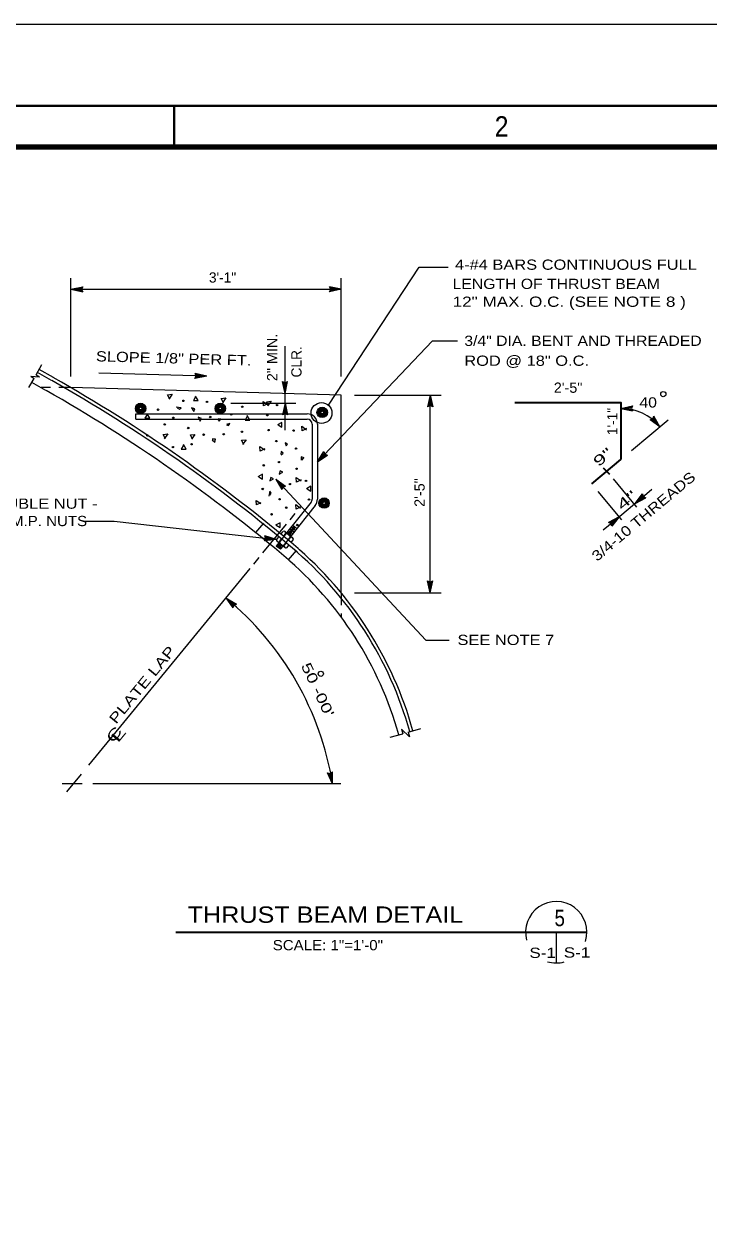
# Model space of a CAD drawing. Extents: x -24.3 to 17.7, y -17.6 to 12.4.
# Drawn here: x -1.17 to 7.19, y -2.28 to 12.39 of the extents above; entities that cross this region are included whole.
import ezdxf
from ezdxf.enums import TextEntityAlignment as Align

# ---------------------------------------------------------------- set-up
doc = ezdxf.new("R2010")
doc.units = 0
doc.header["$LTSCALE"] = 0.05
doc.linetypes.add('MEDIUM_DASHED', pattern=[4.5, 3, -1.5])
doc.layers.add('1', color=7, linetype='Continuous', lineweight=13)
doc.layers.add('2', color=7, linetype='Continuous', lineweight=13)

msp = doc.modelspace()

# ---------------------------------------------------------------- linework, layer by layer
at = {"layer": '1', "lineweight": 40}
msp.add_line((0.65731, 11.3894), (0.65731, 10.8894), dxfattribs=at)
at = {"layer": '1'}
for p, q in [((2.54531, 7.7364), (3.65231, 9.4234)), ((3.65231, 9.4234), (4.00431, 9.4234)), ((-0.60169, 8.0884), (-0.60169, 9.2884)), ((2.70031, 8.0884), (2.70031, 9.2884)), ((-0.60169, 9.1534), (-0.45769, 9.1844)), ((-0.60169, 9.1534), (2.70031, 9.1534)), ((-0.60169, 9.1534), (-0.45769, 9.1224)), ((-0.56469, 9.1534), (-0.47069, 9.1734)), ((-0.56469, 9.1534), (-0.47069, 9.1334)), ((-0.52869, 9.1534), (-0.48369, 9.1634)), ((-0.52869, 9.1534), (-0.48369, 9.1444)), ((-0.48369, 9.1634), (-0.48769, 9.1534)), ((-0.48769, 9.1534), (-0.48369, 9.1444)), ((-0.47069, 9.1734), (-0.47969, 9.1534)), ((-0.47969, 9.1534), (-0.47069, 9.1334)), ((2.70031, 9.1534), (2.55631, 9.1844)), ((2.70031, 9.1534), (2.55631, 9.1224)), ((2.66331, 9.1534), (2.56931, 9.1734)), ((2.57831, 9.1534), (2.56931, 9.1734)), ((2.66331, 9.1534), (2.56931, 9.1334)), ((2.56931, 9.1334), (2.57831, 9.1534)), ((2.62731, 9.1534), (2.58231, 9.1624)), ((2.58631, 9.1534), (2.58231, 9.1624)), ((2.62731, 9.1534), (2.58231, 9.1434)), ((2.58231, 9.1434), (2.58631, 9.1534)), ((2.40831, 7.0454), (3.81431, 8.5234)), ((3.81431, 8.5234), (4.11731, 8.5234)), ((-1.02669, 8.1104), (-0.95569, 8.2334)), ((-1.09369, 8.0914), (-1.05169, 8.0654)), ((-1.09369, 8.0914), (-0.98469, 8.0844)), ((-1.02669, 8.1104), (-0.98469, 8.0844)), ((-1.11669, 7.9524), (-1.05169, 8.0654)), ((2.01331, 7.8824), (1.98231, 8.0264)), ((2.01331, 7.9194), (1.99331, 8.0134)), ((1.99331, 8.0134), (2.01331, 8.0044)), ((2.01331, 7.9554), (2.00331, 8.0004)), ((2.00331, 8.0004), (2.01331, 7.9964)), ((2.01331, 7.8824), (2.04431, 8.0264)), ((2.01331, 7.9194), (2.03331, 8.0134)), ((2.01331, 8.0044), (2.03331, 8.0134)), ((2.01331, 7.9554), (2.02231, 8.0004)), ((2.01331, 7.9964), (2.02231, 8.0004)), ((2.86131, 7.8624), (3.91831, 7.8624)), ((3.78531, 7.8624), (3.75431, 7.7184)), ((3.78531, 7.8254), (3.76531, 7.7314)), ((3.78531, 7.7894), (3.77631, 7.7444)), ((3.78531, 5.4494), (3.78531, 7.8624)), ((3.78531, 7.8624), (3.81631, 7.7184)), ((3.78531, 7.8254), (3.80531, 7.7314)), ((3.78531, 7.7894), (3.79531, 7.7444)), ((1.34931, 7.7624), (2.14531, 7.7624)), ((2.01331, 7.7624), (1.98231, 7.6184)), ((2.01331, 7.7254), (1.99331, 7.6314)), ((2.01331, 7.6404), (1.99331, 7.6314)), ((2.01331, 7.6894), (2.00431, 7.6444)), ((2.01331, 7.6484), (2.00431, 7.6444)), ((2.01331, 7.7624), (2.04431, 7.6184)), ((2.01331, 7.4344), (2.01331, 7.7624)), ((2.01331, 7.7254), (2.03331, 7.6314)), ((2.01331, 7.6894), (2.02331, 7.6444)), ((2.02331, 7.6444), (2.01331, 7.6484)), ((2.03331, 7.6314), (2.01331, 7.6404)), ((3.78531, 7.7404), (3.76531, 7.7314)), ((3.78531, 7.7484), (3.77631, 7.7444)), ((3.79531, 7.7444), (3.78531, 7.7484)), ((3.80531, 7.7314), (3.78531, 7.7404)), ((6.11231, 7.6994), (6.25631, 7.7304)), ((6.11231, 7.6994), (6.25631, 7.6684)), ((6.14931, 7.6994), (6.24331, 7.7194)), ((6.14931, 7.6994), (6.24331, 7.6794)), ((6.18531, 7.6994), (6.23031, 7.7094)), ((6.18531, 7.6994), (6.23031, 7.6904)), ((6.23031, 7.7094), (6.22631, 7.6994)), ((6.22631, 7.6994), (6.23031, 7.6904)), ((6.24331, 7.7194), (6.23431, 7.6994)), ((6.23431, 7.6994), (6.24331, 7.6794)), ((6.24231, 7.1834), (6.69231, 7.5604)), ((6.59131, 7.4754), (6.47131, 7.5604)), ((6.48831, 7.5584), (6.50931, 7.5654)), ((6.56631, 7.5024), (6.48831, 7.5584)), ((6.50431, 7.5554), (6.51431, 7.5594)), ((6.54231, 7.5294), (6.50431, 7.5554)), ((6.50931, 7.5654), (6.51731, 7.5854)), ((6.51431, 7.5594), (6.51831, 7.5684)), ((6.59131, 7.4754), (6.51731, 7.6024)), ((6.56631, 7.5024), (6.51731, 7.5854)), ((6.54231, 7.5294), (6.51831, 7.5684)), ((2.40831, 7.0454), (2.48531, 7.1714)), ((2.40831, 7.0454), (2.53031, 7.1284)), ((2.43431, 7.0724), (2.48431, 7.1544)), ((2.43431, 7.0724), (2.51331, 7.1264)), ((2.45831, 7.0984), (2.48231, 7.1374)), ((2.45831, 7.0984), (2.49631, 7.1244)), ((2.48231, 7.1374), (2.48731, 7.1284)), ((2.48431, 7.1544), (2.49231, 7.1334)), ((2.48731, 7.1284), (2.49631, 7.1244)), ((2.49231, 7.1334), (2.51331, 7.1264)), ((1.89931, 6.8344), (1.97531, 6.7084)), ((1.92431, 6.8074), (2.00331, 6.7524)), ((1.92431, 6.8074), (1.97431, 6.7254)), ((1.94931, 6.7814), (1.97331, 6.7424)), ((1.94931, 6.7814), (1.98731, 6.7554)), ((1.97731, 6.7514), (1.97331, 6.7424)), ((1.98731, 6.7554), (1.97731, 6.7514)), ((2.00331, 6.7524), (1.98231, 6.7454)), ((6.31131, 6.4944), (6.02331, 6.8394)), ((1.98231, 6.7454), (1.97431, 6.7254)), ((6.12431, 6.3384), (5.83631, 6.6834)), ((6.28731, 6.5404), (6.49231, 6.7134)), ((6.28731, 6.5404), (6.37731, 6.6574)), ((6.28731, 6.5404), (6.41731, 6.6094)), ((6.31531, 6.5644), (6.37431, 6.6404)), ((6.31531, 6.5644), (6.40031, 6.6094)), ((6.34331, 6.5874), (6.37131, 6.6244)), ((6.34331, 6.5874), (6.38331, 6.6094)), ((6.37131, 6.6244), (6.37431, 6.6144)), ((6.37431, 6.6404), (6.38031, 6.6194)), ((6.37431, 6.6144), (6.38331, 6.6094)), ((6.38031, 6.6194), (6.40031, 6.6094)), ((6.10131, 6.3844), (6.28131, 6.5354)), ((-0.45769, 6.3214), (-0.07569, 6.3214)), ((2.07431, 6.3394), (2.13831, 6.4174)), ((5.89931, 6.2154), (6.09231, 6.3774)), ((6.09231, 6.3774), (5.96231, 6.3084)), ((6.06431, 6.3534), (5.97931, 6.3084)), ((5.99931, 6.2994), (5.97931, 6.3084)), ((6.03631, 6.3304), (5.99631, 6.3084)), ((6.00531, 6.3044), (5.99631, 6.3084)), ((6.09231, 6.3774), (6.00231, 6.2614)), ((6.06431, 6.3534), (6.00531, 6.2774)), ((6.03631, 6.3304), (6.00831, 6.2934)), ((1.74231, 5.9344), (2.02931, 6.2844)), ((6.00531, 6.2774), (5.99931, 6.2994)), ((6.00831, 6.2934), (6.00531, 6.3044)), ((1.90731, 6.0984), (1.76731, 6.1454)), ((1.77531, 6.0934), (1.78631, 6.1124)), ((1.87031, 6.1024), (1.77531, 6.0934)), ((1.87031, 6.1024), (1.77931, 6.1334)), ((1.78631, 6.1124), (1.77931, 6.1334)), ((1.78931, 6.1014), (1.79431, 6.1114)), ((1.83431, 6.1064), (1.78931, 6.1014)), ((1.83431, 6.1064), (1.79131, 6.1204)), ((1.79431, 6.1114), (1.79131, 6.1204)), ((1.63131, 5.7984), (1.69831, 5.8804)), ((-0.38369, 3.3434), (1.58731, 5.7454)), ((3.78531, 5.4494), (3.75431, 5.5934)), ((3.78531, 5.4864), (3.76531, 5.5804)), ((3.76531, 5.5804), (3.78531, 5.5714)), ((3.78531, 5.4494), (3.81631, 5.5934)), ((3.78531, 5.4864), (3.80531, 5.5804)), ((3.78531, 5.5714), (3.80531, 5.5804)), ((2.86131, 5.4494), (3.91831, 5.4494)), ((3.78531, 5.5224), (3.77531, 5.5674)), ((3.77531, 5.5674), (3.78531, 5.5634)), ((3.78531, 5.5224), (3.79431, 5.5674)), ((3.78531, 5.5634), (3.79431, 5.5674)), ((1.29031, 5.3854), (1.41831, 5.3114)), ((1.29031, 5.3854), (1.37631, 5.2654)), ((1.31731, 5.3604), (1.40131, 5.3124)), ((1.31731, 5.3604), (1.37431, 5.2824)), ((1.34431, 5.3364), (1.37231, 5.2994)), ((1.34431, 5.3364), (1.38431, 5.3134)), ((1.37531, 5.3094), (1.37231, 5.2994)), ((1.38131, 5.3034), (1.37431, 5.2824)), ((1.38431, 5.3134), (1.37531, 5.3094)), ((1.40131, 5.3124), (1.38131, 5.3034)), ((3.73231, 4.8704), (4.01631, 4.8704)), ((3.29731, 3.6874), (3.45031, 3.7294)), ((3.43531, 3.7864), (3.45031, 3.7294)), ((3.53231, 3.6914), (3.43531, 3.7864)), ((3.51731, 3.7484), (3.67231, 3.7914)), ((3.51731, 3.7484), (3.53231, 3.6914)), ((-0.65069, 3.0184), (-0.47169, 3.2364)), ((2.59231, 3.1174), (2.53231, 3.2514)), ((2.58431, 3.1534), (2.54531, 3.2414)), ((2.54531, 3.2414), (2.56731, 3.2364)), ((2.57731, 3.1884), (2.55831, 3.2304)), ((2.55831, 3.2304), (2.56831, 3.2284)), ((2.56731, 3.2364), (2.58431, 3.2494)), ((2.56831, 3.2284), (2.57631, 3.2344)), ((2.57731, 3.1884), (2.57631, 3.2344)), ((2.58431, 3.1534), (2.58431, 3.2494)), ((2.59231, 3.1174), (2.59231, 3.2644)), ((-0.46469, 3.1174), (-0.71069, 3.1174)), ((2.69431, 3.1174), (-0.33269, 3.1174))]:
    msp.add_line(p, q, dxfattribs=at)
at = {"layer": '1', "lineweight": 25}
for p, q in [((-0.83769, 8.0404), (-1.01069, 8.1384)), ((-0.81669, 8.0764), (-0.98969, 8.1744)), ((1.05731, 8.0914), (-0.26169, 8.1274)), ((1.05731, 8.0914), (0.91231, 8.0644)), ((1.05731, 8.0914), (0.91431, 8.1264)), ((0.92631, 8.0754), (0.93531, 8.0944)), ((1.02031, 8.0924), (0.92631, 8.0754)), ((1.02031, 8.0924), (0.92731, 8.1154)), ((0.93531, 8.0944), (0.92731, 8.1154)), ((0.98431, 8.0934), (0.93931, 8.1034)), ((0.94331, 8.0944), (0.93931, 8.1034)), ((0.93931, 8.0844), (0.94331, 8.0944)), ((0.98431, 8.0934), (0.93931, 8.0844)), ((-0.90669, 7.9184), (-1.07969, 8.0164)), ((0.19131, 7.6324), (2.28331, 7.6324)), ((0.19131, 7.5674), (0.19131, 7.6324)), ((0.19131, 7.5674), (2.28331, 7.5674)), ((2.34331, 7.5074), (2.34331, 6.5924)), ((2.40831, 7.5074), (2.40831, 6.5924)), ((2.33031, 6.5544), (2.03231, 6.1794)), ((2.38131, 6.5144), (2.08431, 6.1384)), ((1.96231, 6.1644), (1.98931, 6.1984)), ((1.99531, 6.1384), (2.02231, 6.1724)), ((2.01231, 6.1954), (2.10531, 6.1214)), ((2.09031, 6.1474), (2.04031, 6.1874)), ((2.10531, 6.1664), (2.05531, 6.2064)), ((2.08431, 6.1684), (2.06031, 6.1874)), ((2.12231, 6.1874), (2.07231, 6.2274)), ((2.09931, 6.1874), (2.07531, 6.2064)), ((2.13931, 6.2084), (2.08931, 6.2484)), ((2.11631, 6.2084), (2.09231, 6.2274)), ((2.15631, 6.2304), (2.10631, 6.2704)), ((2.13331, 6.2304), (2.10931, 6.2494)), ((1.93731, 6.0584), (1.90631, 6.0194)), ((1.93431, 6.1324), (1.90731, 6.0984)), ((2.00931, 6.0014), (1.91631, 6.0754)), ((1.96831, 5.9944), (1.91831, 6.0344)), ((1.94931, 5.9984), (1.92531, 6.0174)), ((1.98031, 6.0094), (1.93031, 6.0494)), ((1.96131, 6.0124), (1.93731, 6.0314)), ((1.96731, 6.1054), (1.94031, 6.0714)), ((2.02631, 6.0584), (1.99931, 6.0244)), ((2.05931, 6.0324), (2.03231, 5.9984)), ((2.05431, 6.0914), (2.08131, 6.1254)), ((2.08731, 6.0644), (2.11431, 6.0984)), ((5.32531, 1.3064), (5.32531, 0.9314))]:
    msp.add_line(p, q, dxfattribs=at)
at = {"layer": '1', "linetype": 'MEDIUM_DASHED'}
for p, q in [((-0.60169, 7.9524), (-0.96669, 7.9524)), ((1.65731, 6.1834), (1.77331, 6.3224)), ((2.03231, 6.1794), (1.93731, 6.0594)), ((2.08331, 6.1394), (1.98831, 6.0174)), ((2.05631, 5.8504), (2.17231, 5.9894)), ((2.70031, 5.4464), (2.70031, 5.1544))]:
    msp.add_line(p, q, dxfattribs=at)
at = {"layer": '1', "lineweight": 35}
for p, q in [((5.75831, 6.7774), (6.11231, 7.0734)), ((5.98031, 6.8914), (5.90131, 6.9704)), ((0.68031, 1.3064), (5.70031, 1.3064))]:
    msp.add_line(p, q, dxfattribs=at)
at = {"layer": '1'}
for points in [[(-24.34269, 12.3894), (17.65731, 12.3894), (17.65731, -17.6106)], [(-0.45769, 9.1844), (-0.47169, 9.1534), (-0.45769, 9.1224)], [(2.55631, 9.1224), (2.57031, 9.1534), (2.55631, 9.1844)], [(2.01331, 7.7624), (2.01331, 7.8824), (2.01331, 8.4584)], [(1.98231, 8.0264), (2.01331, 8.0124), (2.04431, 8.0264)], [(2.04431, 7.6184), (2.01331, 7.6324), (1.98231, 7.6184)], [(3.81631, 7.7184), (3.78531, 7.7324), (3.75431, 7.7184)], [(6.25631, 7.7304), (6.24231, 7.6994), (6.25631, 7.6684)], [(6.47131, 7.5604), (6.50331, 7.5714), (6.51731, 7.6024)], [(2.48531, 7.1714), (2.49831, 7.1394), (2.53031, 7.1284)], [(3.73231, 4.8704), (1.89931, 6.8344), (2.02031, 6.7504)], [(2.02031, 6.7504), (1.98831, 6.7394), (1.97531, 6.7084)], [(6.37731, 6.6574), (6.38631, 6.6244), (6.41731, 6.6094)], [(-0.07569, 6.3214), (1.90731, 6.0984), (1.76031, 6.0834)], [(6.00231, 6.2614), (5.99231, 6.2934), (5.96231, 6.3084)], [(1.76031, 6.0834), (1.77831, 6.1134), (1.76731, 6.1454)], [(3.75431, 5.5934), (3.78531, 5.5794), (3.81631, 5.5934)], [(1.41831, 5.3114), (1.38631, 5.2984), (1.37631, 5.2654)], [(2.53231, 3.2514), (2.56531, 3.2444), (2.59231, 3.2644)]]:
    msp.add_lwpolyline(points, dxfattribs=at)
at = {"layer": '1', "lineweight": 40}
msp.add_lwpolyline([(-23.34269, -16.6106), (-23.34269, 11.3894), (16.65731, 11.3894), (16.65731, -16.6106)], close=True, dxfattribs=at)
at = {"layer": '1', "lineweight": 90}
msp.add_lwpolyline([(-21.84269, 10.8894), (16.15731, 10.8894), (16.15731, -16.1106), (-21.84269, -16.1106)], close=True, dxfattribs=at)
at = {"layer": '1', "lineweight": 25}
for points in [[(0.91231, 8.0644), (0.92731, 8.0954), (0.91431, 8.1264)], [(2.70031, 5.4464), (2.70031, 7.8624), (-0.60169, 7.9524)], [(1.98831, 6.0184), (1.95631, 5.9794), (1.90631, 6.0194)]]:
    msp.add_lwpolyline(points, dxfattribs=at)
at = {"layer": '1', "lineweight": 35}
msp.add_lwpolyline([(4.81931, 7.7714), (6.11231, 7.7714), (6.11231, 7.0734)], dxfattribs=at)
at = {"layer": '1', "lineweight": 25}
for centre, radius in [((6.63231, 7.8734), 0.03178), ((0.249, 7.69913), 0.0638), ((0.249, 7.69913), 0.05316), ((0.249, 7.69913), 0.0443), ((0.249, 7.69913), 0.03692), ((0.249, 7.69913), 0.03077), ((0.249, 7.69913), 0.02564), ((0.249, 7.69913), 0.02136), ((0.249, 7.69913), 0.01781), ((1.22222, 7.69888), 0.0638), ((1.22222, 7.69888), 0.05316), ((1.22222, 7.69888), 0.0443), ((1.22222, 7.69888), 0.03692), ((1.22222, 7.69888), 0.03077), ((1.22222, 7.69888), 0.02564), ((1.22222, 7.69888), 0.02136), ((1.22222, 7.69888), 0.01781), ((2.46685, 7.65005), 0.0638), ((2.46685, 7.65005), 0.05316), ((2.46685, 7.65005), 0.0443), ((2.46685, 7.65005), 0.03692), ((2.46685, 7.65005), 0.03077), ((2.46685, 7.65005), 0.02564), ((2.46685, 7.65005), 0.02136), ((2.46685, 7.65005), 0.01781), ((2.48944, 6.54408), 0.0638), ((2.48944, 6.54408), 0.05316), ((2.48944, 6.54408), 0.0443), ((2.48944, 6.54408), 0.03692), ((2.48944, 6.54408), 0.03077), ((2.48944, 6.54408), 0.02564), ((2.48944, 6.54408), 0.02136), ((2.48944, 6.54408), 0.01781), ((2.44931, 4.4604), 0.03178)]:
    msp.add_circle(centre, radius, dxfattribs=at)
at = {"layer": '1'}
msp.add_circle((2.45831, 7.6424), 0.12746, dxfattribs=at)
at = {"layer": '1', "lineweight": 25}
for centre, radius, start, end in [((-10.43391, -8.8871), 19.49949, 49.71979, 60.45013), ((-10.43391, -8.8871), 19.45893, 49.71979, 60.45013), ((-10.43391, -8.8871), 19.31838, 49.71979, 60.45013), ((2.28331, 7.5074), 0.125, 0, 90), ((2.28331, 7.5074), 0.06, 0, 90), ((2.28331, 6.59196), 0.06, 321.57105, 0), ((2.28331, 6.59196), 0.125, 321.57105, 0), ((1.99802, 6.17551), 0.02449, 352.69615, 110.8362), ((2.01848, 6.10705), 0.06546, 16.27468, 86.64295), ((1.9316, 6.09428), 0.02449, 172.69615, 290.8362), ((2.00315, 6.08974), 0.06546, 196.27468, 266.64295), ((2.0236, 6.02128), 0.02449, 172.69615, 290.8362), ((2.09002, 6.10251), 0.02449, 352.69615, 110.8362), ((-0.85001, 2.52878), 4.59422, 15.60734, 49.61534), ((-0.85001, 2.52878), 4.41359, 15.60734, 49.61534), ((-0.85001, 2.52878), 4.55414, 15.60734, 49.61534), ((5.32531, 1.3064), 0.375, 342.70891, 195.26862), ((5.32531, 1.3064), 0.375, 253.4742, 284.92162)]:
    msp.add_arc(centre, radius, start, end, dxfattribs=at)
at = {"layer": '1'}
for centre, radius, start, end in [((6.11231, 7.0754), 0.62405, 39.86435, 90), ((-1.058, 2.52878), 3.69796, 9.16136, 50.57539)]:
    msp.add_arc(centre, radius, start, end, dxfattribs=at)
at = {"layer": '2'}
for p, q in [((1.12231, 7.3144), (1.15431, 7.2884)), ((2.21631, 7.0664), (2.24431, 7.0964))]:
    msp.add_line(p, q, dxfattribs=at)
for points in [[(0.60631, 7.8124), (0.57831, 7.8664), (0.63431, 7.8724), (0.59231, 7.8124)], [(0.92031, 7.8404), (0.89431, 7.7944), (0.95231, 7.7944), (0.92031, 7.8484)], [(1.26231, 7.7684), (1.23431, 7.8204), (1.29031, 7.8264), (1.24831, 7.7684)], [(1.80431, 7.7564), (1.75031, 7.7304), (1.74431, 7.7844), (1.80431, 7.7444)], [(1.81431, 7.7284), (1.78631, 7.7804), (1.84231, 7.7864), (1.80031, 7.7284)], [(0.32831, 7.6244), (0.30231, 7.5804), (0.36031, 7.5804), (0.32831, 7.6344)], [(0.69631, 7.7044), (0.72231, 7.6884), (0.74631, 7.7044), (0.68231, 7.7144)], [(1.19031, 7.5664), (1.20831, 7.5444), (1.23031, 7.5664), (1.19431, 7.5704)], [(1.29831, 7.4984), (1.32431, 7.4884), (1.33831, 7.5164), (1.29831, 7.5044)], [(1.55231, 7.6024), (1.52631, 7.5564), (1.58431, 7.5564), (1.55231, 7.6124)], [(1.92831, 7.4964), (1.97431, 7.4684), (1.97431, 7.5284), (1.92031, 7.4964)], [(2.27431, 7.4524), (2.22031, 7.4244), (2.21631, 7.4804), (2.27431, 7.4384)], [(0.55231, 7.3284), (0.52631, 7.3824), (0.58031, 7.3884), (0.53831, 7.3284)], [(0.88431, 7.3244), (0.85831, 7.3764), (0.91231, 7.3824), (0.87031, 7.3244)], [(0.77231, 7.2484), (0.74631, 7.2024), (0.80431, 7.2024), (0.77231, 7.2564)], [(1.15431, 7.2844), (1.16231, 7.3244), (1.12231, 7.3244)], [(1.50831, 7.2564), (1.48231, 7.3104), (1.53631, 7.3164), (1.49431, 7.2564)], [(1.76431, 7.2044), (1.71031, 7.1784), (1.70431, 7.2324), (1.76431, 7.1924)], [(2.03231, 7.2404), (2.04231, 7.2684), (2.01431, 7.2804), (2.02831, 7.2404)], [(1.96431, 7.1324), (1.98831, 7.1524), (1.96431, 7.1744), (1.96031, 7.1384)], [(2.24831, 7.0964), (2.20831, 7.1064), (2.20831, 7.0664)], [(1.69231, 6.8644), (1.73631, 6.8364), (1.73631, 6.8964), (1.68231, 6.8644)], [(2.20831, 6.8284), (2.15431, 6.8004), (2.14831, 6.8564), (2.20831, 6.8144)], [(2.28431, 6.7164), (2.32831, 6.6884), (2.32831, 6.7484), (2.27431, 6.7164)], [(1.82631, 6.6404), (1.84431, 6.6664), (1.82631, 6.6884), (1.81631, 6.6264)], [(1.71831, 6.5484), (1.66431, 6.5224), (1.66031, 6.5764), (1.71831, 6.5364)], [(2.20231, 6.4964), (2.14831, 6.4684), (2.14431, 6.5244), (2.20231, 6.4824)], [(1.90631, 6.2724), (1.95231, 6.2444), (1.95231, 6.3044), (1.89631, 6.2724)]]:
    msp.add_lwpolyline(points, dxfattribs=at)
for points in [[(0.87031, 7.7044), (0.89831, 7.6604), (0.91231, 7.6924)], [(0.95031, 7.5904), (0.97831, 7.5444), (0.99231, 7.5764)], [(1.94031, 6.8944), (1.98631, 6.9204), (1.95431, 6.9364)], [(1.82631, 6.8144), (1.87231, 6.8404), (1.84031, 6.8564)]]:
    msp.add_lwpolyline(points, close=True, dxfattribs=at)
for centre in [(0.77196, 7.7913), (1.05996, 7.77797), (0.46264, 7.6833), (1.35595, 7.62464), (1.49061, 7.7193), (1.91593, 7.7398), (0.54397, 7.50331), (0.64663, 7.58464), (1.09996, 7.59397), (1.79594, 7.6153), (0.33198, 7.36864), (0.83063, 7.45931), (1.01862, 7.37798), (1.26528, 7.38331), (1.48528, 7.41398), (1.81194, 7.43447), (2.11726, 7.42914), (0.64263, 7.22598), (0.87063, 7.26198), (1.9066, 7.29981), (2.14793, 7.20915), (1.93727, 7.04382), (1.75327, 7.00382), (2.15326, 6.96249), (2.07193, 6.77449), (2.26926, 6.81449), (1.73994, 6.71583), (1.9466, 6.5905), (2.02793, 6.48783), (2.30526, 6.5865), (1.84794, 6.4065), (2.16259, 6.27584)]:
    msp.add_circle(centre, 0.00867, dxfattribs=at)

# ---------------------------------------------------------------- texts
at = {"layer": '1'}
for s, height, width, p in [('2', 0.25, 0.9, (4.65781, 11.0144)), ('2\'-5"', 0.125, 1.05, (5.46981, 7.8894)), ('40', 0.125, 1.15, (6.44781, 7.7094)), ('3/4" M.P. NUTS', 0.125, 1.1, (-1.05519, 6.2624)), ('SEE NOTE 7', 0.125, 1.2, (4.70981, 4.8114)), ('THRUST BEAM DETAIL', 0.2, 1.15, (2.50631, 1.4214)), ('5', 0.2, 0.85, (5.36781, 1.3804)), ('SCALE: 1"=1\'-0"', 0.125, 1.1, (2.53581, 1.0864)), ('S-1', 0.125, 1.25, (5.15931, 0.9934)), ('S-1', 0.125, 1.25, (5.57931, 0.9974))]:
    msp.add_text(s, height=height, dxfattribs=dict(at, width=width)).set_placement(p, align=Align.CENTER)
for s, width, p in [('4-#4 BARS CONTINUOUS FULL', 1.2, (4.08831, 9.3904)), ('LENGTH OF THRUST BEAM', 1.15, (4.05931, 9.1564)), ('12" MAX. O.C. (SEE NOTE 8 )', 1.25, (4.05931, 8.9384)), ('3/4" DIA. BENT AND THREADED', 1.15, (4.20231, 8.4614)), ('ROD @ 18" O.C.', 1.2, (4.20231, 8.2184))]:
    msp.add_text(s, height=0.125, dxfattribs=dict(at, width=width)).set_placement(p)
msp.add_text('3\'-1"', height=0.125, dxfattribs=at).set_placement((1.24981, 9.2344), align=Align.CENTER)
for s, rotation, width, p in [('2" MIN.', 90, 1.05, (1.91831, 8.0314)), ('PLATE LAP', 50.632, 1.3, (-0.05069, 3.8384)), ('C', 50.632, 1.6, (-0.08769, 3.6064))]:
    msp.add_text(s, height=0.125, rotation=rotation, dxfattribs=dict(at, width=width)).set_placement(p)
for s, rotation, width, p in [('SLOPE 1/8" PER FT.', 358.437, 1.2, (0.65116, 8.24751)), ('9"', 39.857, 1.6, (5.93362, 7.05731)), ('3/4-10 THREADS', 39.901, 1.2, (6.43083, 6.33334)), ('2\'-5"', 90, 1.05, (3.71831, 6.6719)), ('4"', 40.023, 1.7, (6.22619, 6.53067)), ("50 -00'", 295.174, 1.4, (2.35563, 4.23912)), ('L', 50.632, 1.85, (0.02635, 3.67648))]:
    msp.add_text(s, height=0.125, rotation=rotation, dxfattribs=dict(at, width=width)).set_placement(p, align=Align.CENTER)
for s, p in [('CLR.', (2.21431, 8.2669)), ('1\'-1"', (6.07231, 7.5389))]:
    msp.add_text(s, height=0.125, rotation=90, dxfattribs=at).set_placement(p, align=Align.CENTER)
at = {"layer": '1', "width": 1.2}
msp.add_text('DOUBLE NUT -', height=0.125, dxfattribs=at).set_placement((-0.27669, 6.4744), align=Align.RIGHT)

doc.saveas('drawing.dxf')
